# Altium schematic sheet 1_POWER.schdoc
size 302 x 215 mm; Symbol: Sheet_A4; Device: Sheet_A4; @Project Name: Yuzukilizard; REV: 1.0; Date: 2022-10-08; Sheet: 1/1; Draw By: GloomyGhost; Company: YuzukiHD
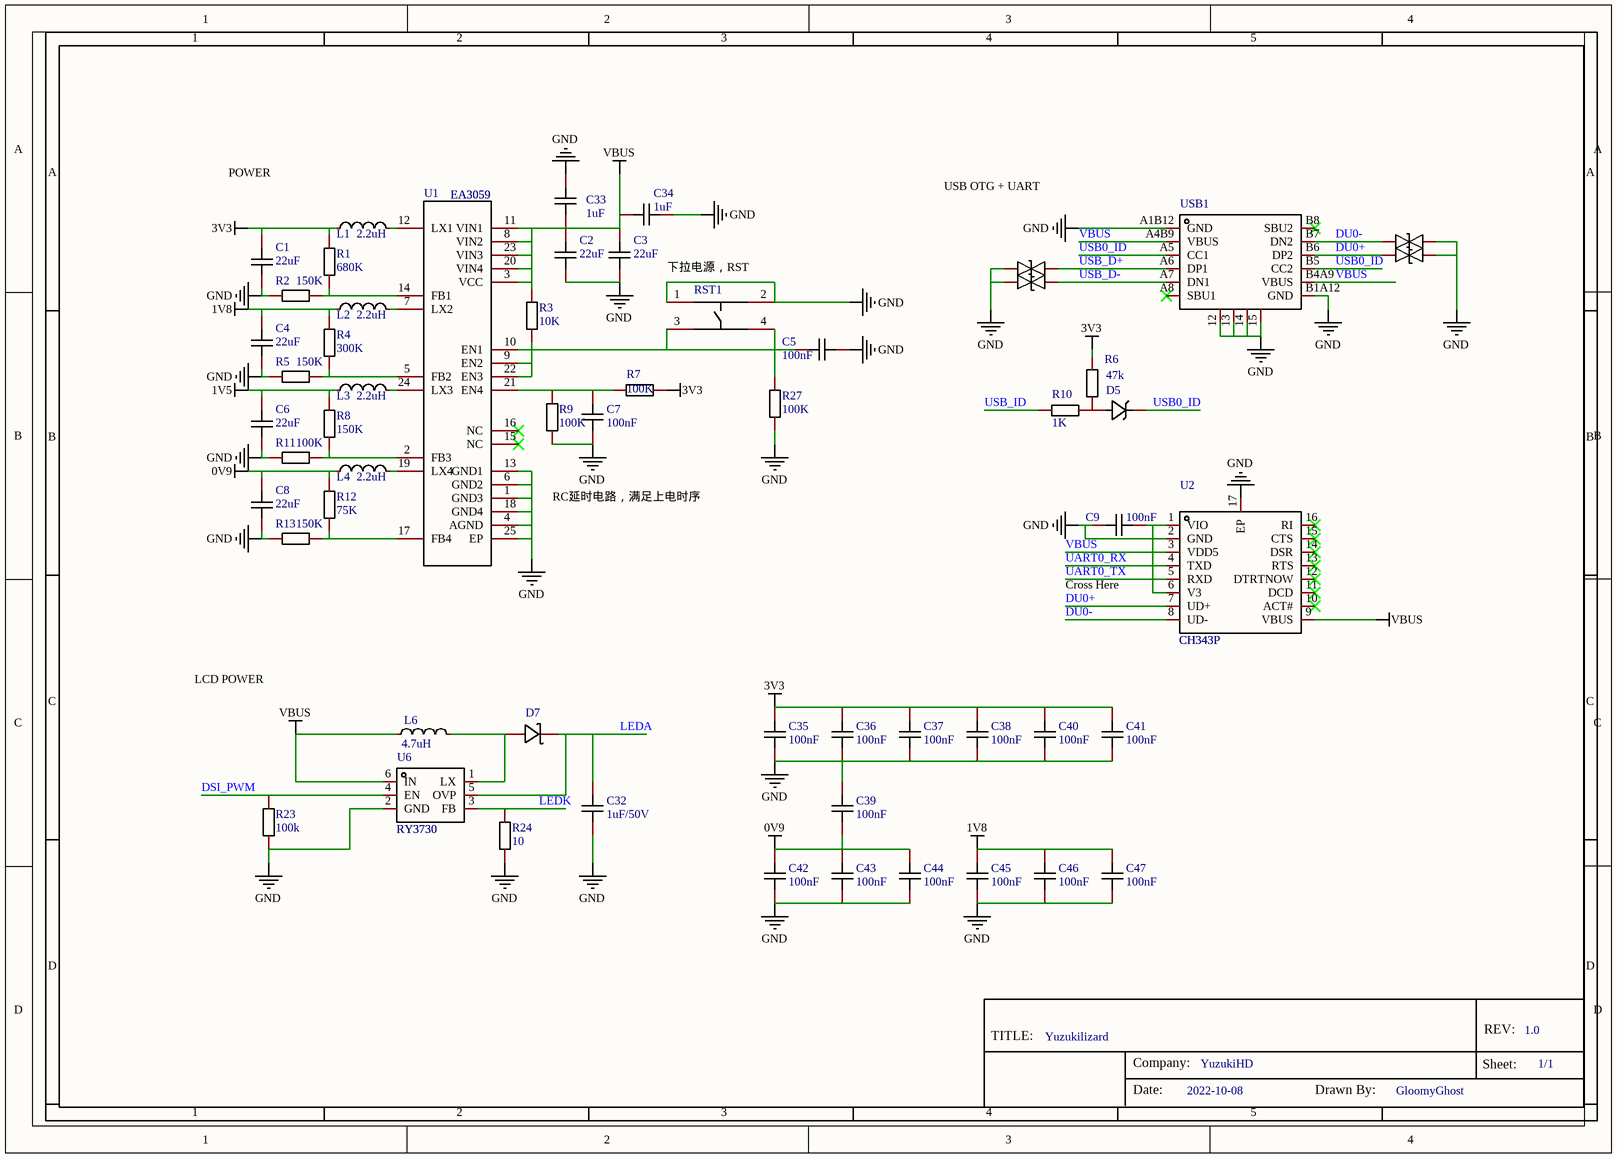
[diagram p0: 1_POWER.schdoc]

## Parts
C1  value 22uF  [C0603 NSK]  (hidden comment: CAP_0603)
C2  value 22uF  [C0603 NSK]  (hidden comment: CAP_0603)
C3  value 22uF  [C0603 NSK]  (hidden comment: CAP_0603)
C4  value 22uF  [C0603 NSK]  (hidden comment: CAP_0603)
C5  value 100nF  [C0402]  (hidden comment: CAP_0402)
C6  value 22uF  [C0603 NSK]  (hidden comment: CAP_0603)
C7  value 100nF  [C0402]  (hidden comment: CAP_0402)
C8  value 22uF  [C0603 NSK]  (hidden comment: CAP_0603)
C9  value 100nF  [C0402]  (hidden comment: CAP_0402)
C32  value 1uF/50V  [C0603 NSK]  (hidden comment: CAP_0603)
C33  value 1uF  [C0402]  (hidden comment: CAP_0402)
C34  value 1uF  [C0402]  (hidden comment: CAP_0402)
C35  value 100nF  [C0402]  (hidden comment: CAP_0402)
C36  value 100nF  [C0402]  (hidden comment: CAP_0402)
C37  value 100nF  [C0402]  (hidden comment: CAP_0402)
C38  value 100nF  [C0402]  (hidden comment: CAP_0402)
C39  value 100nF  [C0402]  (hidden comment: CAP_0402)
C40  value 100nF  [C0402]  (hidden comment: CAP_0402)
C41  value 100nF  [C0402]  (hidden comment: CAP_0402)
C42  value 100nF  [C0402]  (hidden comment: CAP_0402)
C43  value 100nF  [C0402]  (hidden comment: CAP_0402)
C44  value 100nF  [C0402]  (hidden comment: CAP_0402)
C45  value 100nF  [C0402]  (hidden comment: CAP_0402)
C46  value 100nF  [C0402]  (hidden comment: CAP_0402)
C47  value 100nF  [C0402]  (hidden comment: CAP_0402)
D1  0402ESDA-05N  [D0402]  (value not drawn)
D2  0402ESDA-05N  [D0402]  (value not drawn)
D3  0402ESDA-05N  [D0402]  (value not drawn)
D4  0402ESDA-05N  [D0402]  (value not drawn)
D5  1N5819-SOD523  [SOD-523_L1.2-W0.8-LS1.6-FD]  (value not drawn)
D7  B5819WS_C22624  [SOD-323_L1.8-W1.3-LS2.5-RD]  (value not drawn)
L1  value 2.2uH  [IND-SMD_L2.0-W1.6]  (hidden comment: CKCS201610-2.2uH/M)
L2  value 2.2uH  [IND-SMD_L2.0-W1.6]  (hidden comment: CKCS201610-2.2uH/M)
L3  value 2.2uH  [IND-SMD_L2.0-W1.6]  (hidden comment: CKCS201610-2.2uH/M)
L4  value 2.2uH  [IND-SMD_L2.0-W1.6]  (hidden comment: CKCS201610-2.2uH/M)
L6  value 4.7uH  [IND-SMD_L2.5-W2.0_SWPA252010S1R0MT]  (hidden comment: WPN252012H4R7MT)
R1  value 680K  [R0402]  (hidden comment: Res_0402)
R2  value 150K  [R0402]  (hidden comment: Res_0402)
R3  value 10K  [R0402]  (hidden comment: Res_0402)
R4  value 300K  [R0402]  (hidden comment: Res_0402)
R5  value 150K  [R0402]  (hidden comment: Res_0402)
R6  value 47k  [R0402]  (hidden comment: Res_0402)
R7  value 100K  [R0402]  (hidden comment: Res_0402)
R8  value 150K  [R0402]  (hidden comment: Res_0402)
R9  value 100K  [R0402]  (hidden comment: Res_0402)
R10  value 1K  [R0402]  (hidden comment: Res_0402)
R11  value 100K  [R0402]  (hidden comment: Res_0402)
R12  value 75K  [R0402]  (hidden comment: Res_0402)
R13  value 150K  [R0402]  (hidden comment: Res_0402)
R23  value 100k  [R0402]  (hidden comment: Res_0402)
R24  value 10  [R0402]  (hidden comment: Res_0402)
R27  value 100K  [R0402]  (hidden comment: Res_0402)
RST1  PTS810SJM250SMTRLFS  [KEY-SMD_4P-L4.2-W3.2-P2.20-LS4.6]  (value not drawn)
U1  EA3059  [QFN-24_L4.0-W4.0-P0.50-TL-EP2.7]
U2  CH343P  [TQFN-16_L3.0-W3.0-P0.50-BL-EP1.7]
U6  RY3730  [SOT-23-6_L2.9-W1.6-P0.95-LS2.8-BL]
USB1  TYPEC-304-BCP16  [USB-C-SMD_TYPEC-304-BCP16-1]  (value not drawn)

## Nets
0V9: C8.2 C39.1 C42.2 C43.2 C44.2 L4.1 R12.2
1V5: C6.2 L3.1 R8.2
1V8: C4.2 C45.2 C46.2 C47.2 L2.1 R4.2
3V3: C1.2 C35.2 C36.2 C37.2 C38.2 C40.2 C41.2 L1.1 R1.2 R6.2 R7.2
GND: C1.1 C2.1 C3.1 C4.1 C5.2 C6.1 C7.1 C8.1 C9.1 C32.1 C33.2 C34.2 C35.1 C36.1 C37.1 C38.1 C39.2 C40.1 C41.1 C42.1 C43.1 C44.1 C45.1 C46.1 C47.1 D1.2 D2.2 D3.2 D4.2 R2.2 R5.2 R9.1 R11.2 R13.2 R23.1 R24.1 R27.1 RST1.1 RST1.2 U1.1(GND3) U1.4(AGND) U1.6(GND2) U1.13(GND1) U1.18(GND4) U1.25(EP) U2.2(GND) U2.17(EP) U6.2(GND) USB1.12 USB1.13 USB1.14 USB1.15 USB1.A1B12(GND) USB1.B1A12(GND)
VBUS: C2.2 C3.2 C33.1 C34.1 L6.1 R3.2 U1.3(VCC) U1.8(VIN2) U1.11(VIN1) U1.20(VIN4) U1.23(VIN3) U2.3(VDD5) U2.9(VBUS) U6.6(IN) USB1.A4B9(VBUS) USB1.B4A9(VBUS)
DSI_PWM: R23.2 U6.4(EN)
DU0+: D2.1 U2.7(UD+) USB1.B6(DP2)
DU0-: D1.1 U2.8(UD-) USB1.B7(DN2)
LEDA: C32.2 D7.1(K) U6.5(OVP)
LEDK: R24.2 U6.3(FB)
UART0_RX: U2.4(TXD)
UART0_TX: U2.5(RXD)
USB0_ID: D5.2(K) USB1.A5(CC1) USB1.B5(CC2)
USB_D+: D4.1 USB1.A6(DP1)
USB_D-: D3.1 USB1.A7(DN1)
USB_ID: R10.1
NetC5_1: C5.1 R3.1 R27.2 RST1.3 RST1.4 U1.9(EN2) U1.10(EN1) U1.22(EN3)
NetC7_2: C7.2 R7.1 R9.2 U1.21(EN4)
NetC9_2: C9.2 U2.1(VIO) U2.6(V3)
NetD5_1: D5.1(A) R6.1 R10.2
NetD7_2: D7.2(A) L6.2 U6.1(LX)
NetL1_2: L1.2 U1.12(LX1)
NetL2_2: L2.2 U1.7(LX2)
NetL3_2: L3.2 U1.24(LX3)
NetL4_2: L4.2 U1.19(LX4)
NetR1_1: R1.1 R2.1 U1.14(FB1)
NetR4_1: R4.1 R5.1 U1.5(FB2)
NetR8_1: R8.1 R11.1 U1.2(FB3)
NetR12_1: R12.1 R13.1 U1.17(FB4)

Not connected (* = marked no-connect by the designer): U1 15(NC)* 16(NC)*; U2 10(ACT#)* 11(DCD)* 12(DTRTNOW)* 13(RTS)* 14(DSR)* 15(CTS)* 16(RI)*; USB1 A8(SBU1)* B8(SBU2)*

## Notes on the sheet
- POWER
- USB OTG + UART
- (near RST1) 下拉电源，RST
- RC延时电路，满足上电时序
- Cross Here
- LCD POWER

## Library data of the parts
C1-C4 C6 C8 C32 = CAP_0603: 容值:100nF;精度:±10%;额定电压:50V;温度系数:X7R;; Symbol: C1210X7R475K630NT; Convert to PCB: yes
C5 C7 C9 C33-C47 = CAP_0402: 容值:100nF;精度:±10%;额定电压:16V;温度系数:X7R;; Symbol: C1210X7R475K630NT; Convert to PCB: yes
D1-D4 = 0402ESDA-05N: 极性:Bidirectional;反向关断电压（典型值）:5V;击穿电压（最小值）:-;箝位电压:50V;峰值脉冲电流（10/1000us）:-;; Manufacturer: BORN伯恩半导体; Add into BOM: yes; Voltage - Reverse Standoff (Typ): 5V; Voltage - Clamping (Max) @ Ipp: 50V
D5 = 1N5819-SOD523: Add into BOM: yes
D7 = B5819WS_C22624: 直流反向耐压(Vr):40V;平均整流电流(Io):1A;正向压降(Vf):600mV@1A;; Manufacturer: CJ（江苏长电/长晶）; Add into BOM: yes; Reverse Voltage (Vr): 40V; Average Rectified Current (Io): 1A
L1-L4 = CKCS201610-2.2uH/M: 电感值:2.2uH;精度:±20%;额定电流:1.1A;直流电阻(DCR):264mΩ;; Manufacturer: CENKER(岑科); Symbol: CKCS201610-2.2UH/M-N; Add into BOM: yes; Tolerance: ±20%; Rated Current: 1.1A; DC Resistance (DCR): 264mΩ
L6 = WPN252012H4R7MT: 电感值:4.7uH;精度:±20%;额定电流:1.25A;直流电阻(DCR):260m;; Manufacturer: Sunlord(顺络); Add into BOM: yes; Rated Current: 1.25A; Tolerance: ±20%; DC Resistance (DCR): 260m
R1-R13 R23 R24 R27 = Res_0402: Symbol: 电阻; Convert to PCB: yes
RST1 = PTS810SJM250SMTRLFS: 触点电流:50mA;额定电压(DC):16V;电路结构:单刀单掷;安装方式:立贴;按钮形状:圆形按钮;带灯:-;开关长度:4.2mm;开关宽度:3.2mm;开关高度:2.5mm;; Manufacturer: C&K; Add into BOM: yes; Contact Current: 50mA; Voltage Rating (DC): 16V; Circuit: 单刀单掷; Actuator Style: 圆形按钮; Switch Length: 4.2mm; Switch Width: 3.2mm; Switch Height: 2.5mm
U1 = EA3059: 充电电池的类型:-;电池单元组数:-;最大充电电流:-;充满的电池组电压:-;最大供应电压:-;; Manufacturer: everanalog(申风); Add into BOM: yes; Pin Type: IN
U2 = CH343P: 类型:-;协议类别:-;驱动器/接收器数:-;数据速率:-;; Manufacturer: WCH(南京沁恒); Add into BOM: yes
U6 = RY3730: 类型:-;拓扑结构:-;内部开关:-;供电电压（最低）:-;供电电压（最高）:-;频率:-;; Manufacturer: RYCHiP(蕊源); Add into BOM: yes
USB1 = TYPEC-304-BCP16: Manufacturer: XUNPU; Pin Type: IN; Add into BOM: yes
